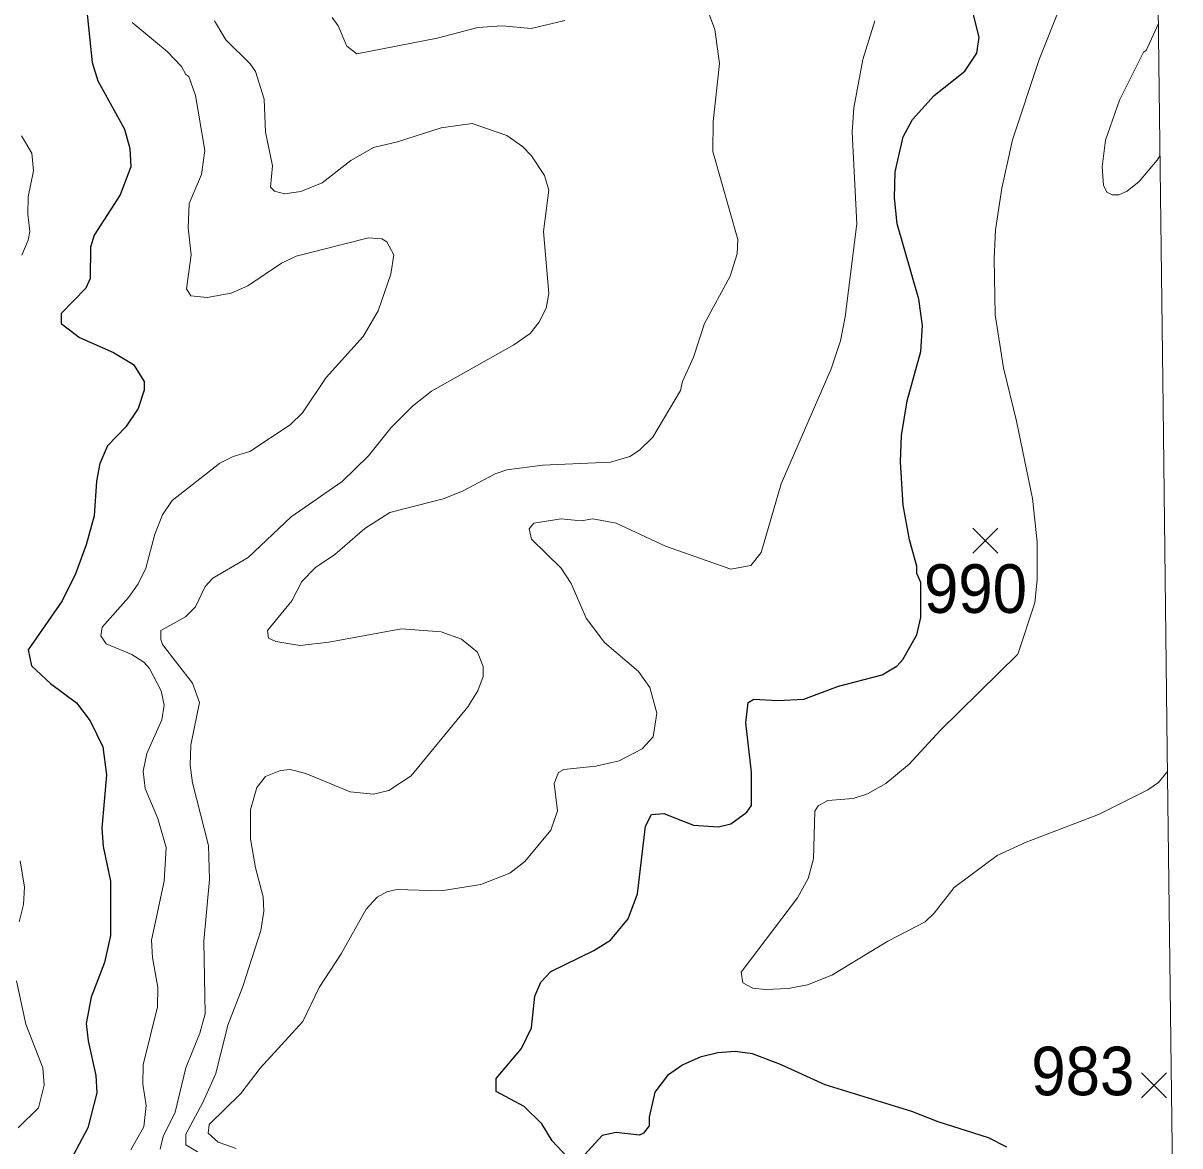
# Model space of a CAD drawing. Extents: x 265 to 291.4, y 7731.5 to 7759.6.
# Drawn here: x 289.514 to 291.417, y 7732.926 to 7734.774 of the extents above; entities that cross this region are included whole.
import ezdxf
from ezdxf.enums import TextEntityAlignment as Align

# ---------------------------------------------------------------- set-up
doc = ezdxf.new("R2010")
doc.units = 0
doc.header["$LTSCALE"] = 0.032
for name, color, linetype, lineweight in [('1', 7, 'Continuous', 25), ('2', 7, 'Continuous', 13), ('21', 7, 'Continuous', 25), ('61', 7, 'Continuous', 13), ('63', 7, 'Continuous', 25)]:
    doc.layers.add(name, color=color, linetype=linetype, lineweight=lineweight)

msp = doc.modelspace()

# ---------------------------------------------------------------- linework, layer by layer
at = {"layer": '1'}
for points in [[(289.6169, 7734.8095), (289.6273, 7734.7093), (289.6368, 7734.6791), (289.6806, 7734.5995), (289.6893, 7734.5677), (289.6909, 7734.5375), (289.6734, 7734.4913), (289.6305, 7734.4253), (289.6249, 7734.4054), (289.6241, 7734.3537), (289.6169, 7734.3378), (289.5764, 7734.2964), (289.5764, 7734.2797), (289.6066, 7734.2566), (289.6623, 7734.232), (289.6957, 7734.2121), (289.7132, 7734.1843), (289.7132, 7734.17), (289.7029, 7734.1397), (289.683, 7734.1095), (289.6527, 7734.0785), (289.64, 7734.0491), (289.6344, 7734.0204), (289.6305, 7733.9631), (289.6177, 7733.9154)], [(290.4077, 7732.9091), (290.3846, 7732.9346), (290.3671, 7732.9624), (290.3384, 7732.9911), (290.2923, 7733.0157), (290.2923, 7733.0372), (290.3337, 7733.0865), (290.3504, 7733.1207), (290.3559, 7733.1724), (290.3655, 7733.1955), (290.3822, 7733.213), (290.453, 7733.248), (290.4801, 7733.2647), (290.5095, 7733.2997), (290.5246, 7733.3411), (290.5381, 7733.4524), (290.5477, 7733.4715), (290.5683, 7733.4731), (290.6169, 7733.454), (290.6583, 7733.4516), (290.6781, 7733.4564), (290.7044, 7733.4755), (290.7123, 7733.4866), (290.7123, 7733.5415), (290.7028, 7733.6227), (290.7068, 7733.6561), (290.7163, 7733.6616), (290.7553, 7733.6592), (290.7983, 7733.6616), (290.8555, 7733.6831), (290.9271, 7733.7014), (290.9518, 7733.7165), (290.9613, 7733.7269), (290.9844, 7733.7675), (290.9907, 7733.7961), (290.9907, 7733.8534), (290.9844, 7733.8685), (290.9844, 7733.8804), (290.9724, 7733.9234), (290.9621, 7733.9806), (290.9573, 7734.0522), (290.9589, 7734.0952), (290.9685, 7734.1525), (290.9907, 7734.2336), (290.9939, 7734.2766), (290.9876, 7734.3195), (290.9518, 7734.4436), (290.9478, 7734.4866), (290.9486, 7734.5295), (290.9621, 7734.5868), (290.9772, 7734.6154), (291.013, 7734.6552), (291.0631, 7734.695), (291.083, 7734.7244), (291.087, 7734.7507), (291.0766, 7734.792)], [(289.6177, 7733.9154), (289.6002, 7733.8677), (289.578, 7733.8231), (289.5223, 7733.7428), (289.5278, 7733.7165), (289.5589, 7733.6871), (289.6018, 7733.6553)], [(289.6018, 7733.6553), (289.6241, 7733.6259), (289.6448, 7733.5829), (289.6511, 7733.5368), (289.6432, 7733.4493), (289.6456, 7733.419), (289.6575, 7733.3618), (289.6575, 7733.2727), (289.648, 7733.2281), (289.6257, 7733.1708), (289.6177, 7733.1279), (289.6209, 7733.0992), (289.6336, 7733.042), (289.6352, 7733.0133), (289.6201, 7732.9561), (289.5827, 7732.8845)], [(291.1323, 7732.9242), (291.1021, 7732.9393), (291.0194, 7732.9656), (290.9764, 7732.9831), (290.8333, 7733.0268), (290.7601, 7733.0602), (290.7139, 7733.0777), (290.6853, 7733.0817), (290.6567, 7733.0793), (290.628, 7733.0722), (290.5994, 7733.0594), (290.5739, 7733.0419), (290.5532, 7733.0149), (290.5437, 7732.9736), (290.5437, 7732.9592), (290.5349, 7732.9473), (290.5278, 7732.9441), (290.4896, 7732.9481), (290.4665, 7732.9433), (290.4315, 7732.9051)]]:
    msp.add_lwpolyline(points, dxfattribs=at)
at = {"layer": '2'}
for points in [[(291.3969, 7733.5425), (291.382, 7733.5241), (291.3646, 7733.5121), (291.2835, 7733.4715), (291.1642, 7733.4262), (291.1165, 7733.4039), (291.0456, 7733.3514), (291.013, 7733.3093), (290.9979, 7733.2949), (290.9367, 7733.2631), (290.8444, 7733.2074), (290.8046, 7733.1915), (290.7728, 7733.1852), (290.7346, 7733.1836), (290.7147, 7733.1859), (290.698, 7733.1947), (290.6956, 7733.2122), (290.7879, 7733.3347), (290.8054, 7733.3665), (290.8142, 7733.3984), (290.8165, 7733.4771), (290.8221, 7733.4859), (290.838, 7733.4946), (290.8794, 7733.4978), (290.9033, 7733.5057), (290.9335, 7733.5224), (290.9717, 7733.5542), (291.0226, 7733.61), (291.1506, 7733.7356), (291.1785, 7733.82), (291.1825, 7733.8581), (291.1825, 7733.9202), (291.1745, 7733.9918), (291.1483, 7734.1191), (291.1268, 7734.2066), (291.1133, 7734.2941), (291.1117, 7734.3863), (291.1141, 7734.4341), (291.1244, 7734.5025), (291.1419, 7734.582), (291.1856, 7734.7141), (291.2191, 7734.7984)], [(290.9152, 7734.7777), (290.8953, 7734.7141), (290.881, 7734.6345), (290.8778, 7734.5948), (290.8858, 7734.4436), (290.8667, 7734.2909), (290.8587, 7734.2511), (290.8436, 7734.205), (290.7609, 7734.0156), (290.7282, 7733.9027), (290.7115, 7733.8812), (290.6781, 7733.8756), (290.5707, 7733.913), (290.4896, 7733.9512), (290.4514, 7733.9584), (290.4323, 7733.9552), (290.3989, 7733.9584), (290.3544, 7733.9512), (290.3464, 7733.9417), (290.3504, 7733.925), (290.3989, 7733.8772), (290.4156, 7733.8518), (290.4403, 7733.7945), (290.4705, 7733.7547), (290.5262, 7733.707), (290.5453, 7733.6807), (290.5564, 7733.6386), (290.5508, 7733.5996), (290.5326, 7733.5797), (290.4944, 7733.5598), (290.4562, 7733.5511), (290.4037, 7733.5455), (290.3949, 7733.5407), (290.3878, 7733.5224), (290.3933, 7733.4779), (290.3822, 7733.4461), (290.3392, 7733.3944), (290.3146, 7733.3753), (290.2669, 7733.3562), (290.2016, 7733.3458), (290.1285, 7733.3482), (290.1125, 7733.3443), (290.0966, 7733.3355), (290.0783, 7733.3156), (290.037, 7733.2424), (290.0012, 7733.1868), (289.9741, 7733.1311), (289.9041, 7733.0539), (289.8723, 7733.0125), (289.8198, 7732.9616), (289.8182, 7732.9473), (289.8349, 7732.9322), (289.8644, 7732.9218)], [(289.8285, 7734.7777), (289.8476, 7734.7467), (289.8874, 7734.7069), (289.8962, 7734.6942), (289.9105, 7734.6489), (289.9129, 7734.5948), (289.924, 7734.5391), (289.9208, 7734.5041), (289.9272, 7734.4977), (289.9439, 7734.4929), (289.971, 7734.4969), (290.006, 7734.5112), (290.0529, 7734.5478), (290.0903, 7734.5693), (290.1301, 7734.5788), (290.2016, 7734.6019), (290.2526, 7734.6091), (290.3098, 7734.5892), (290.3353, 7734.5709), (290.3504, 7734.5558), (290.3719, 7734.5232), (290.379, 7734.4993), (290.3703, 7734.4309), (290.379, 7734.3291)], [(290.4053, 7734.7785), (290.3496, 7734.765), (290.3019, 7734.7698), (290.2621, 7734.7666), (290.1953, 7734.7491), (290.0632, 7734.7236), (290.0465, 7734.7363), (290.0322, 7734.7698), (290.0226, 7734.7833)], [(290.3098, 7734.0387), (290.3687, 7734.0467), (290.4801, 7734.0514), (290.5119, 7734.061), (290.5278, 7734.0713), (290.5501, 7734.0928), (290.5954, 7734.1692), (290.5986, 7734.1843), (290.6169, 7734.2241), (290.6352, 7734.2797), (290.6773, 7734.3577), (290.6885, 7734.3943), (290.6901, 7734.4182), (290.6487, 7734.5629), (290.6495, 7734.6123), (290.6598, 7734.7077), (290.6519, 7734.7634), (290.6431, 7734.7873)], [(289.9391, 7734.3792), (289.8834, 7734.3418), (289.8564, 7734.3299), (289.8166, 7734.3227), (289.7896, 7734.3251), (289.7824, 7734.337), (289.7904, 7734.3927), (289.7856, 7734.4373), (289.7872, 7734.477), (289.8071, 7734.5248), (289.8126, 7734.5645), (289.7975, 7734.6552), (289.7864, 7734.6862), (289.7816, 7734.6894), (289.7745, 7734.7029), (289.7506, 7734.7276), (289.6933, 7734.7753)], [(291.3819, 7734.7736), (291.3615, 7734.7292), (291.3575, 7734.726), (291.3177, 7734.6473), (291.2946, 7734.5812), (291.2891, 7734.5375), (291.2914, 7734.5073), (291.297, 7734.4961), (291.3058, 7734.4913), (291.3169, 7734.4913), (291.3304, 7734.4977), (291.3503, 7734.5136), (291.3798, 7734.5486), (291.3845, 7734.5558)], [(289.5111, 7734.5884), (289.5279, 7734.5598), (289.531, 7734.5311), (289.5223, 7734.4882), (289.5215, 7734.4595), (289.5247, 7734.4309), (289.5223, 7734.4166), (289.5119, 7734.3919)], [(290.1189, 7734.3609), (290.1237, 7734.3927), (290.1125, 7734.4142), (290.1038, 7734.4189), (290.0823, 7734.4205), (289.963, 7734.3903), (289.9391, 7734.3792)], [(289.6909, 7732.9195), (289.7124, 7732.9577), (289.7164, 7732.9927), (289.7108, 7733.0277), (289.7116, 7733.0595), (289.7347, 7733.1549), (289.7355, 7733.1868), (289.7267, 7733.2361), (289.7251, 7733.2647), (289.7458, 7733.3618), (289.749, 7733.4174), (289.7355, 7733.4652), (289.7148, 7733.5145), (289.7116, 7733.5431), (289.7172, 7733.5718), (289.7418, 7733.6275), (289.7458, 7733.6513), (289.741, 7733.6752), (289.722, 7733.7118), (289.7124, 7733.7221), (289.6925, 7733.7348), (289.6504, 7733.7523), (289.6416, 7733.7659), (289.644, 7733.7802), (289.687, 7733.8287), (289.7029, 7733.851), (289.7156, 7733.8772), (289.7307, 7733.9329), (289.7434, 7733.9647), (289.7593, 7733.9886), (289.8373, 7734.0498), (289.8596, 7734.061), (289.8866, 7734.0689), (289.9535, 7734.1127), (289.9733, 7734.1326), (290.0123, 7734.1907), (290.0736, 7734.2583), (290.0982, 7734.3004), (290.1189, 7734.3609)], [(290.379, 7734.3291), (290.3743, 7734.3052), (290.3623, 7734.2813), (290.348, 7734.263), (290.321, 7734.2447), (290.1857, 7734.1684), (290.1547, 7734.1437)], [(290.1547, 7734.1437), (290.1197, 7734.1087), (290.0823, 7734.0618), (290.0386, 7734.0196), (289.955, 7733.9615), (289.8842, 7733.8947), (289.8262, 7733.8605), (289.8134, 7733.847), (289.7975, 7733.8136), (289.7808, 7733.7969), (289.7403, 7733.7746), (289.7403, 7733.7595), (289.7434, 7733.7515), (289.7927, 7733.6879), (289.8039, 7733.6561), (289.7896, 7733.5861), (289.7888, 7733.5527), (289.7927, 7733.524), (289.819, 7733.4206), (289.8206, 7733.3649), (289.811, 7733.2631), (289.8134, 7733.1438), (289.8047, 7733.112), (289.7816, 7733.0547), (289.7641, 7732.9815), (289.7442, 7732.9417), (289.7395, 7732.9211)], [(290.0266, 7733.8995), (290.0759, 7733.9425), (290.1173, 7733.9687), (290.2048, 7733.991), (290.2366, 7734.0037), (290.2907, 7734.0323), (290.3098, 7734.0387)], [(289.8007, 7732.9163), (289.7816, 7732.9282), (289.7816, 7732.9457), (289.8095, 7732.9974), (289.8309, 7733.0452), (289.8508, 7733.1247), (289.8755, 7733.1883), (289.9049, 7733.2806), (289.9097, 7733.3124), (289.9089, 7733.3363), (289.8962, 7733.384), (289.8882, 7733.4318), (289.8882, 7733.4795), (289.8986, 7733.5161), (289.9129, 7733.5344), (289.9375, 7733.5439), (289.9535, 7733.5455), (289.9789, 7733.5391), (290.0521, 7733.5089), (290.0903, 7733.5049), (290.1157, 7733.5113), (290.1523, 7733.5352), (290.2454, 7733.6489), (290.2621, 7733.6752), (290.2708, 7733.699), (290.2708, 7733.715), (290.2613, 7733.7388), (290.2351, 7733.7603), (290.2016, 7733.7722), (290.1364, 7733.777), (290.0171, 7733.7555), (289.9694, 7733.7499), (289.9296, 7733.7563), (289.9176, 7733.7619), (289.9161, 7733.7746), (289.9558, 7733.8231), (289.9725, 7733.855), (289.9948, 7733.878), (290.0266, 7733.8995)], [(289.5088, 7733.3952), (289.5159, 7733.3522), (289.5143, 7733.3236), (289.5072, 7733.2949)], [(289.5032, 7733.1979), (289.5183, 7733.1263), (289.5461, 7733.0547), (289.5485, 7733.0261), (289.539, 7732.9887), (289.5056, 7732.9561)]]:
    msp.add_lwpolyline(points, dxfattribs=at)
at = {"layer": '21'}
for p, q in [((291.0767, 7733.9427), (291.1179, 7733.9015)), ((291.1179, 7733.9427), (291.0767, 7733.9015)), ((291.3542, 7733.0464), (291.3954, 7733.0052)), ((291.3954, 7733.0464), (291.3542, 7733.0052))]:
    msp.add_line(p, q, dxfattribs=at)
at = {"layer": '63', "lineweight": 13}
msp.add_lwpolyline([(291.4172, 7731.8831), (291.4103, 7732.448), (291.4034, 7733.0129), (291.3965, 7733.5778), (291.3896, 7734.1427), (291.3827, 7734.7076), (291.3758, 7735.2725), (291.3689, 7735.8374), (291.362, 7736.4023), (291.3551, 7736.9672), (291.3482, 7737.5321), (291.3413, 7738.097), (291.3345, 7738.6619), (291.3276, 7739.2268), (291.3207, 7739.7916), (291.3138, 7740.3565)], dxfattribs=at)

# ---------------------------------------------------------------- texts
at = {"layer": '61', "width": 0.95}
for s, p in [('990', (291.0809, 7733.8034)), ('983', (291.2575, 7733.0095))]:
    msp.add_text(s, height=0.08, dxfattribs=at).set_placement(p, align=Align.CENTER)

doc.saveas('drawing.dxf')
